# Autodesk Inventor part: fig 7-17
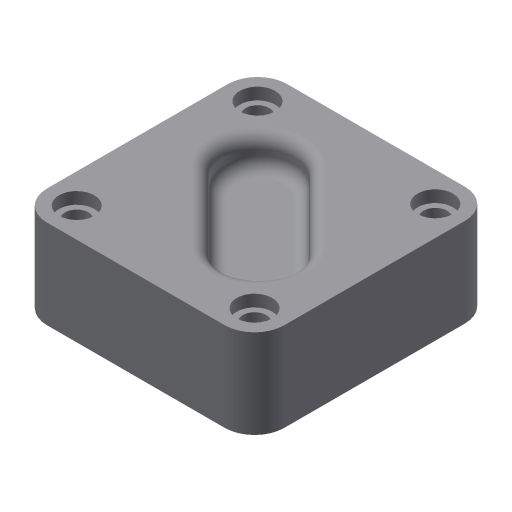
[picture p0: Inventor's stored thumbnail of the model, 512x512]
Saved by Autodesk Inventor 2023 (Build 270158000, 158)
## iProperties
Created: 2001-12
Part Number: fig 7-17
Document SubType Name: Modeling
Designer: Renu Muthoo
Density: 1 g/cm^3
Material: Generic
Appearance: Default
Control State: 0
Master: False
Checked Out: False
Shininess: 77.0
Angle Display Precision: 2
Document Length Units: 11269
Document Angle Units: 11279
Document Time Units: 11290
Document Mass Units: 11283
Document Length Units Precision: 3
Document Angle Units Precision: 2
Density: 0.0
Volumn: 0.0
Area: 0.0
PropertySet Name: Model Information
Author: Renu Muthoo
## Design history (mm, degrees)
sketch "Sketch1"
  geometry: L1 (-20, 20)-(20, 20); L2 (20, 20)-(20, -20.5); L3 (20, -20.5)-(-20, -20.5); L4 (-20, -20.5)-(-20, 20); 1 further point
  constraints: 8 end point, 2 parallel, 1 horizontal, 1 perpendicular, 1 other
  dimensions: "d0" = 40 distance of L1.start L1.end; "d1" = 40.5 distance of L3.end L1.start; "d100" = 20 distance from line of L4 point (0, 0); "d101" = 20 distance from line of L1 point (0, 0)
extrude "Extrusion1" new body sketch "Sketch1" distance "d2" = 15; taper "d3" = 0 deg
workplane "Work Plane1"
workplane "Work Plane2"
workplane "Work Plane3"
fillet "Fillet1" dims "d32" = 5
hole "Hole3" diameter "d66" = 4; stored, may be unused: countersink angle "d70" = 90 deg, drill point angle "d72" = 118 deg; dims "d64" = 10, "d65" = 10, "d67" = 6, "d68" = 6, "d69" = 2, "d71" = 8
hole "Hole4" diameter "d75" = 4; stored, may be unused: countersink angle "d79" = 90 deg, drill point angle "d81" = 118 deg; dims "d73" = 10, "d74" = 10, "d76" = 6, "d77" = 6, "d78" = 2, "d80" = 8
hole "Hole5" diameter "d84" = 4; stored, may be unused: countersink angle "d88" = 90 deg, drill point angle "d90" = 118 deg; dims "d82" = 10, "d83" = 10, "d85" = 6, "d86" = 6, "d87" = 2, "d89" = 8
hole "Hole6" diameter "d93" = 4; stored, may be unused: countersink angle "d97" = 90 deg, drill point angle "d99" = 118 deg; dims "d91" = 10, "d92" = 10, "d94" = 6, "d95" = 6, "d96" = 2, "d98" = 8
fillet "Fillet2" dims "d61" = 2
body "Solid1"
sketch "Sketch8"
  geometry: L1 (-9.844, 1.64)-(1.983, -10.187); L2 (10.469, -1.701)-(-1.358, 10.126); A1 r 6 centre (-5.601, 5.883) between (-1.358, 10.126) and (-9.844, 1.64); A2 r 6 centre (6.226, -5.944) between (1.983, -10.187) and (10.469, -1.701)
  constraints: 4 end point, 4 point on circle, 4 tangent, 2 centre point, 1 parallel
  dimensions: "d29" = 6 radius of A2
extrude "Extrusion2" cut sketch "Sketch8" distance "d30" = 5; taper "d31" = 0 deg
